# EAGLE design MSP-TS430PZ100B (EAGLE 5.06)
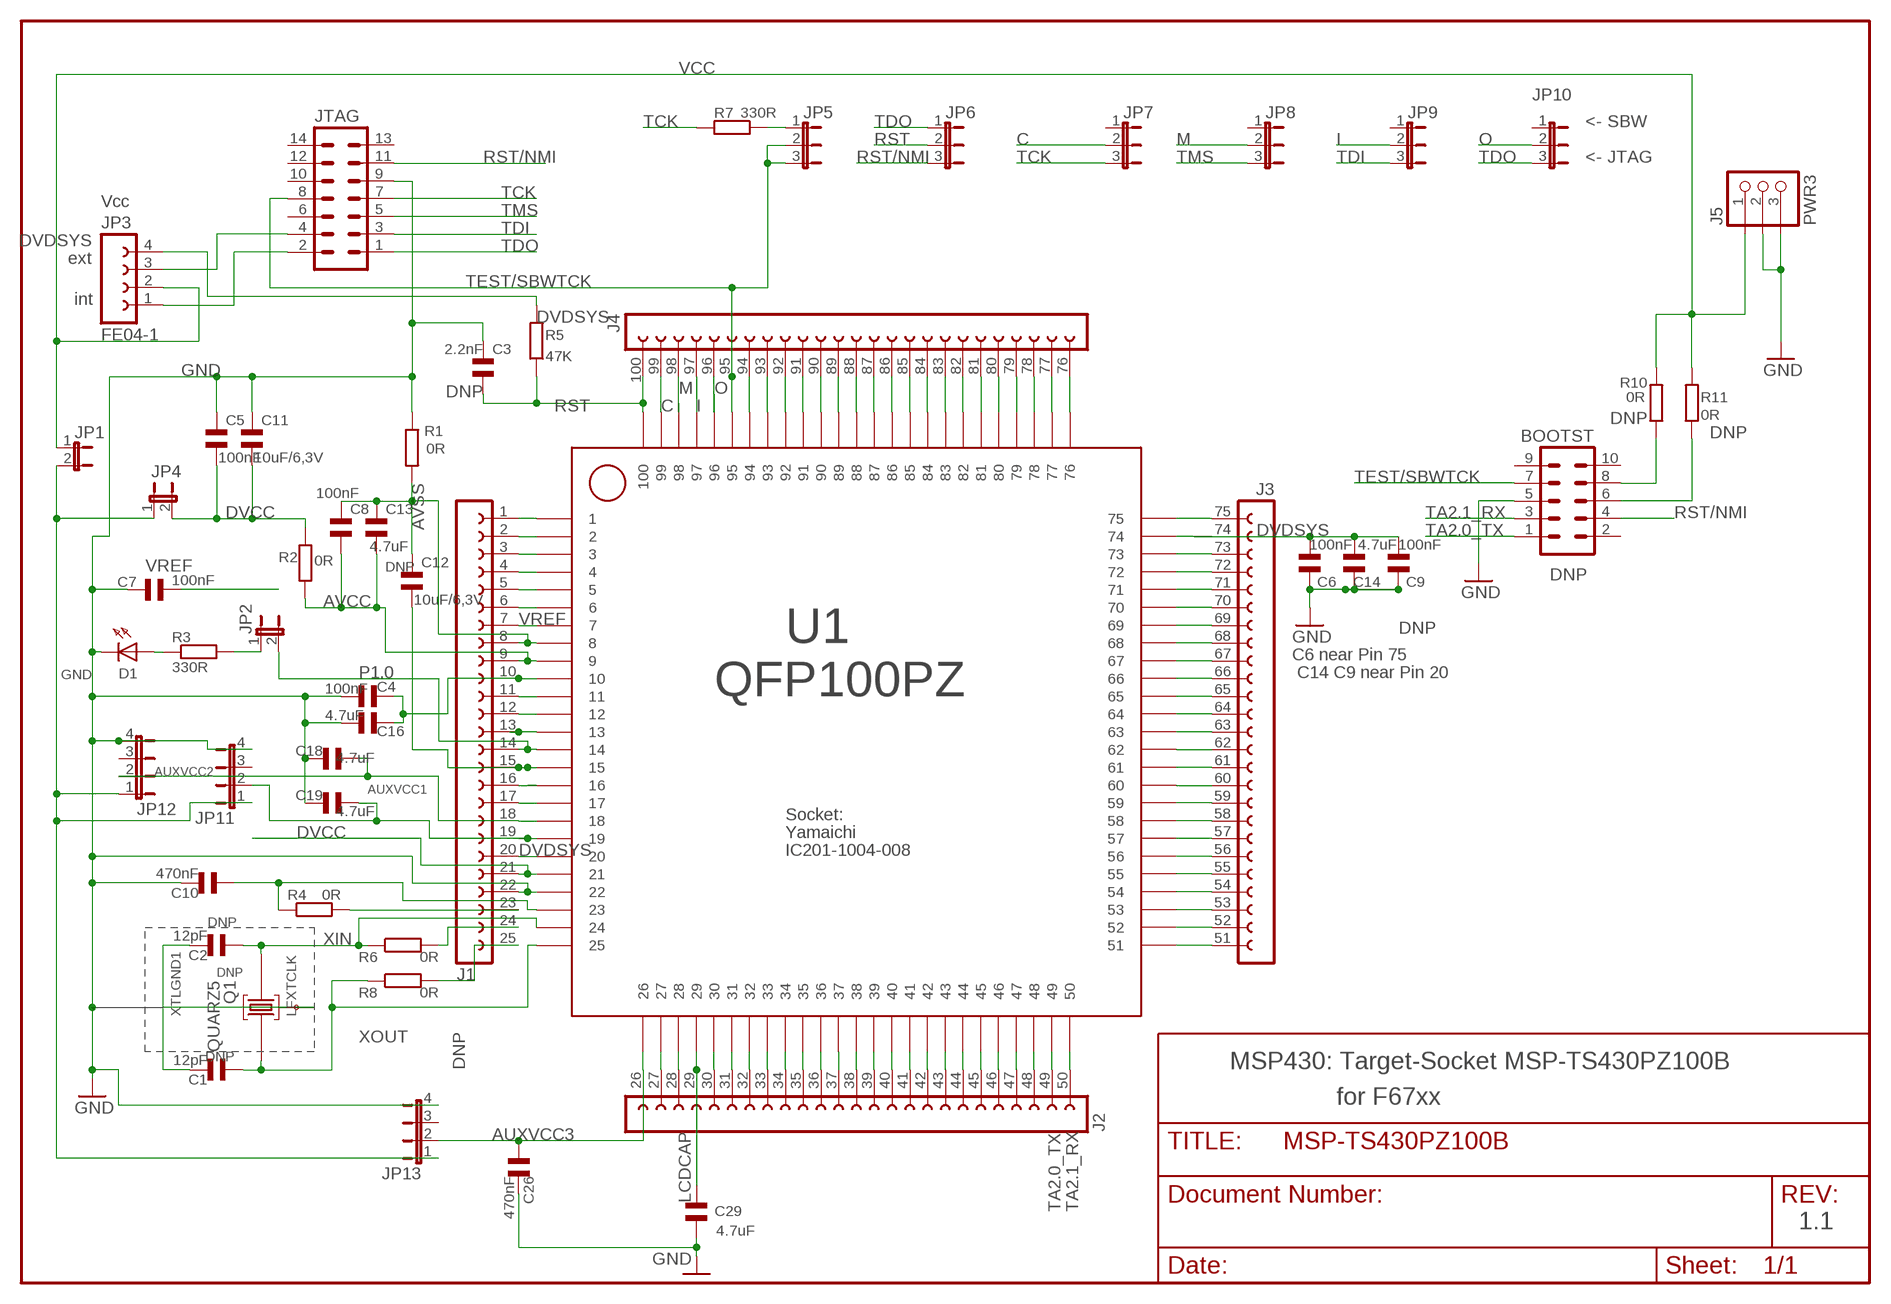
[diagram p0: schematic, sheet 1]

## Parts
BOOTST  ML10  [ML10]
C1  12pF  CSMD0805  [CSMD0805]
C2  12pF  CSMD0805  [CSMD0805]
C3  2.2nF  CSMD0805  [CSMD0805]
C4  100nF  CSMD0805  [CSMD0805]
C5  100nF  CSMD0805  [CSMD0805]
C6  100nF  CSMD0805  [CSMD0805]
C7  100nF  CSMD0805  [CSMD0805]
C8  100nF  CSMD0805  [CSMD0805]
C9  100nF  CSMD0805  [CSMD0805]
C10  470nF  CSMD0805  [CSMD0805]
C11  10uF/6,3V  CSMD0805  [CSMD0805]
C12  10uF/6,3V  CSMD0805  [CSMD0805]
C13  4.7uF  CSMD0805  [CSMD0805]
C14  4.7uF  CSMD0805  [CSMD0805]
C16  4.7uF  CSMD0805  [CSMD0805]
C18  4.7uF  CSMD0805  [CSMD0805]
C19  4.7uF  CSMD0805  [CSMD0805]
C26  470nF  CSMD0805  [CSMD0805]
C29  4.7uF  CSMD0805  [CSMD0805]
D1  LED30805  [DIODE_0805]
J1  FE25-1A1  [FE25-1A1]
J2  FE25-1A2  [FE25-1A2]
J3  FE25-1A3  [FE25-1A3]
J4  FE25-1A4  [FE25-1A4]
J5  PWR3  [PWR3]
JP1  JP1E  [JP1]
JP2  JP1E  [JP1]
JP3  FE04-1  [FE04-1]
JP4  JP1E  [JP1]
JP5  JP2ESMALLPAD  [JP2Z]
JP6  JP2ESMALLPAD  [JP2Z]
JP7  JP2ESMALLPAD  [JP2Z]
JP8  JP2ESMALLPAD  [JP2Z]
JP9  JP2ESMALLPAD  [JP2Z]
JP10  JP2ESMALLPAD  [JP2Z]
JP11  JP4E  [JP4]
JP12  JP4E  [JP4]
JP13  JP4E  [JP4]
JTAG  ML14  [ML14]
Q1  QUARZ5  [QUARZ5]
R1  0R  R_0805  [0805]
R2  0R  R_0805  [0805]
R3  330R  R_0805  [0805]
R4  0R  R_0805  [0805]
R5  47K  R_0805  [0805]
R6  0R  R_0805  [0805]
R7  330R  R_0805  [0805]
R8  0R  R_0805  [0805]
R10  0R  R_0805  [0805]
R11  0R  R_0805  [0805]
U1  QFP100PZ  [QFP100PZ]

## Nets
AUXVCC1: C19.2 J1.19 JP11.2 U1.P19
AUXVCC2: C18.2 J1.18 JP12.2 U1.P18
AUXVCC3: C26.1 J2.26 JP13.2 U1.P26
AVCC: C8.1 C13.1 J1.9 R2.1 U1.P9
AVSS: C8.2 C12.2 C13.2 J1.8 R1.2 U1.P8
C: J4.99 JP7.2 U1.P99
DVCC: C5.1 C11.1 J1.21 JP4.2 R2.2 U1.P21
DVDSYS: C6.2 C9.2 C14.2 J1.20 J3.74 JP3.4 R5.2 U1.P20 U1.P74
GND: BOOTST.5 C3.1 C4.2 C5.2 C6.1 C7.2 C9.1 C10.2 C11.2 C14.1 C16.2 C18.1 C19.1 C26.2 C29.1 D1.K J1.22 J5.2 J5.3 JP11.4 JP12.4 JP13.4 JTAG.9 R1.1 U1.P22
I: J4.97 JP9.2 U1.P97
LCDCAP: C29.2 J2.29 U1.P29
M: J4.98 JP8.2 U1.P98
MSP_VCC: JP1.2 JP4.1 JP11.1 JP12.1 JP13.1
N$1: JP2.1 R3.2
N$2: J3.62 U1.P62
N$3: J1.11 U1.P11
N$4: J3.64 U1.P64
N$5: J4.83 U1.P83
N$6: J4.76 U1.P76
N$7: JP3.1 JTAG.2
N$8: J4.85 U1.P85
N$9: J1.3 U1.P3
N$10: J4.84 U1.P84
N$11: J4.82 U1.P82
N$12: J1.4 U1.P4
N$13: J1.5 U1.P5
N$14: J4.81 U1.P81
N$15: J1.6 U1.P6
N$16: J2.46 U1.P46
N$17: J4.94 U1.P94
N$18: D1.A R3.1
N$20: J4.93 U1.P93
N$21: J2.42 U1.P42
N$22: J1.1 U1.P1
N$23: JP3.3 JTAG.4
N$24: J4.92 U1.P92
N$25: J3.60 U1.P60
N$26: J1.13 U1.P13
N$27: J4.91 U1.P91
N$28: J1.24 R6.2
N$29: J1.25 R8.2
N$31: J2.37 U1.P37
N$32: J1.23 R4.2
N$33: J3.61 U1.P61
N$34: J2.39 U1.P39
N$35: J4.90 U1.P90
N$36: J3.63 U1.P63
N$37: J1.12 U1.P12
N$39: J4.89 U1.P89
N$40: J2.28 U1.P28
N$42: BOOTST.8 R10.1
N$43: J2.30 U1.P30
N$44: J2.31 U1.P31
N$45: J2.32 U1.P32
N$46: J2.33 U1.P33
N$47: J2.34 U1.P34
N$48: J2.35 U1.P35
N$49: BOOTST.6 R11.1
N$50: J2.36 U1.P36
N$51: J4.88 U1.P88
N$52: J4.87 U1.P87
N$53: J1.2 U1.P2
N$54: J2.38 U1.P38
N$55: J2.40 U1.P40
N$56: J2.41 U1.P41
N$57: JP5.1 R7.1
N$58: J2.43 U1.P43
N$59: J2.44 U1.P44
N$60: J2.45 U1.P45
N$62: J2.47 U1.P47
N$63: J2.48 U1.P48
N$66: J3.51 U1.P51
N$67: J3.52 U1.P52
N$68: J3.53 U1.P53
N$69: J4.86 U1.P86
N$70: J3.54 U1.P54
N$71: J3.55 U1.P55
N$72: J3.56 U1.P56
N$73: J3.57 U1.P57
N$74: J3.58 U1.P58
N$75: J3.59 U1.P59
N$80: J4.80 U1.P80
N$81: J4.79 U1.P79
N$84: J4.78 U1.P78
N$86: J4.77 U1.P77
N$87: J3.65 U1.P65
N$88: J3.66 U1.P66
N$89: J3.67 U1.P67
N$90: J3.68 U1.P68
N$91: J3.69 U1.P69
N$92: J3.70 U1.P70
N$93: J3.71 U1.P71
N$94: J3.72 U1.P72
N$95: J3.73 U1.P73
N$97: J3.75 U1.P75
O: J4.96 JP10.2 U1.P96
P1.0: J1.14 JP2.2 U1.P14
P2.2: J2.27 U1.P27
RST: C3.2 J4.100 JP6.2 R5.1 U1.P100
RST/NMI: BOOTST.4 JP6.3 JTAG.11
TA2.0_TX: BOOTST.1 J2.49 U1.P49
TA2.1_RX: BOOTST.3 J2.50 U1.P50
TCK: JP7.3 JTAG.7 R7.2
TDI: JP9.3 JTAG.3
TDO: JP6.1 JP10.3 JTAG.1
TEST/SBWTCK: BOOTST.7 J4.95 JP5.2 JP5.3 JTAG.8 U1.P95
TMS: JP8.3 JTAG.5
UCA0RXD: J1.16 U1.P16
UCA0TXD: J1.17 U1.P17
VASYS: C4.1 C16.1 J1.10 U1.P10
VCC: J5.1 JP1.1 JP3.2 R10.2 R11.2
VCORE: C10.1 R4.1 U1.P23
VEREF+: C12.1 J1.15 U1.P15
VREF: C7.1 J1.7 U1.P7
XIN: C2.1 Q1.2 R6.1 U1.P24
XOUT: C1.1 Q1.1 R8.1 U1.P25
XTLGND1: C1.2 C2.2 Q1.GND@0
Unconnected: BOOTST.2 BOOTST.9 BOOTST.10 JP7.1 JP8.1 JP9.1 JP10.1 JP11.3 JP12.3 JP13.3 JTAG.6 JTAG.10 JTAG.12 JTAG.13 JTAG.14

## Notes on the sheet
- <- SBW
- <- JTAG
- Vcc
- DVDSYS
- ext
- int
- DNP
- DNP
- DNP
- DNP
- DNP
- DNP
- C6 near Pin 75
- GND
- C14 C9 near Pin 20
- Socket:
- Yamaichi
- IC201-1004-008
- DNP
- DNP
- LFXTCLK
- DNP
- DNP | MSP430: Target-Socket MSP-TS430PZ100B
- for F67xx
- 1.1

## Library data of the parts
BOOTST = con-ml:ML10
C1-C14 C16 C18 C19 C26 C29 = cap:CSMD0805
D1 = MSP430:LED3
J1 = CON-LSTA:FE25-1A1
J2 = CON-LSTA:FE25-1A2
J3 = CON-LSTA:FE25-1A3
J4 = CON-LSTA:FE25-1A4
J5 = MSP430:PWR3
JP1 JP2 JP4 = jumper:JP1E: JUMPER
JP3 = scon-lsta:FE04-1
JP5-JP10 = jumper:JP2E: JUMPER
JP11-JP13 = sjumper:JP4E: JUMPER
JTAG = con-ml:ML14
Q1 = sMSP430:QUARZ5
R1-R8 R10 R11 = smd:R_0805
U1 = MSP430:QFP100PZ

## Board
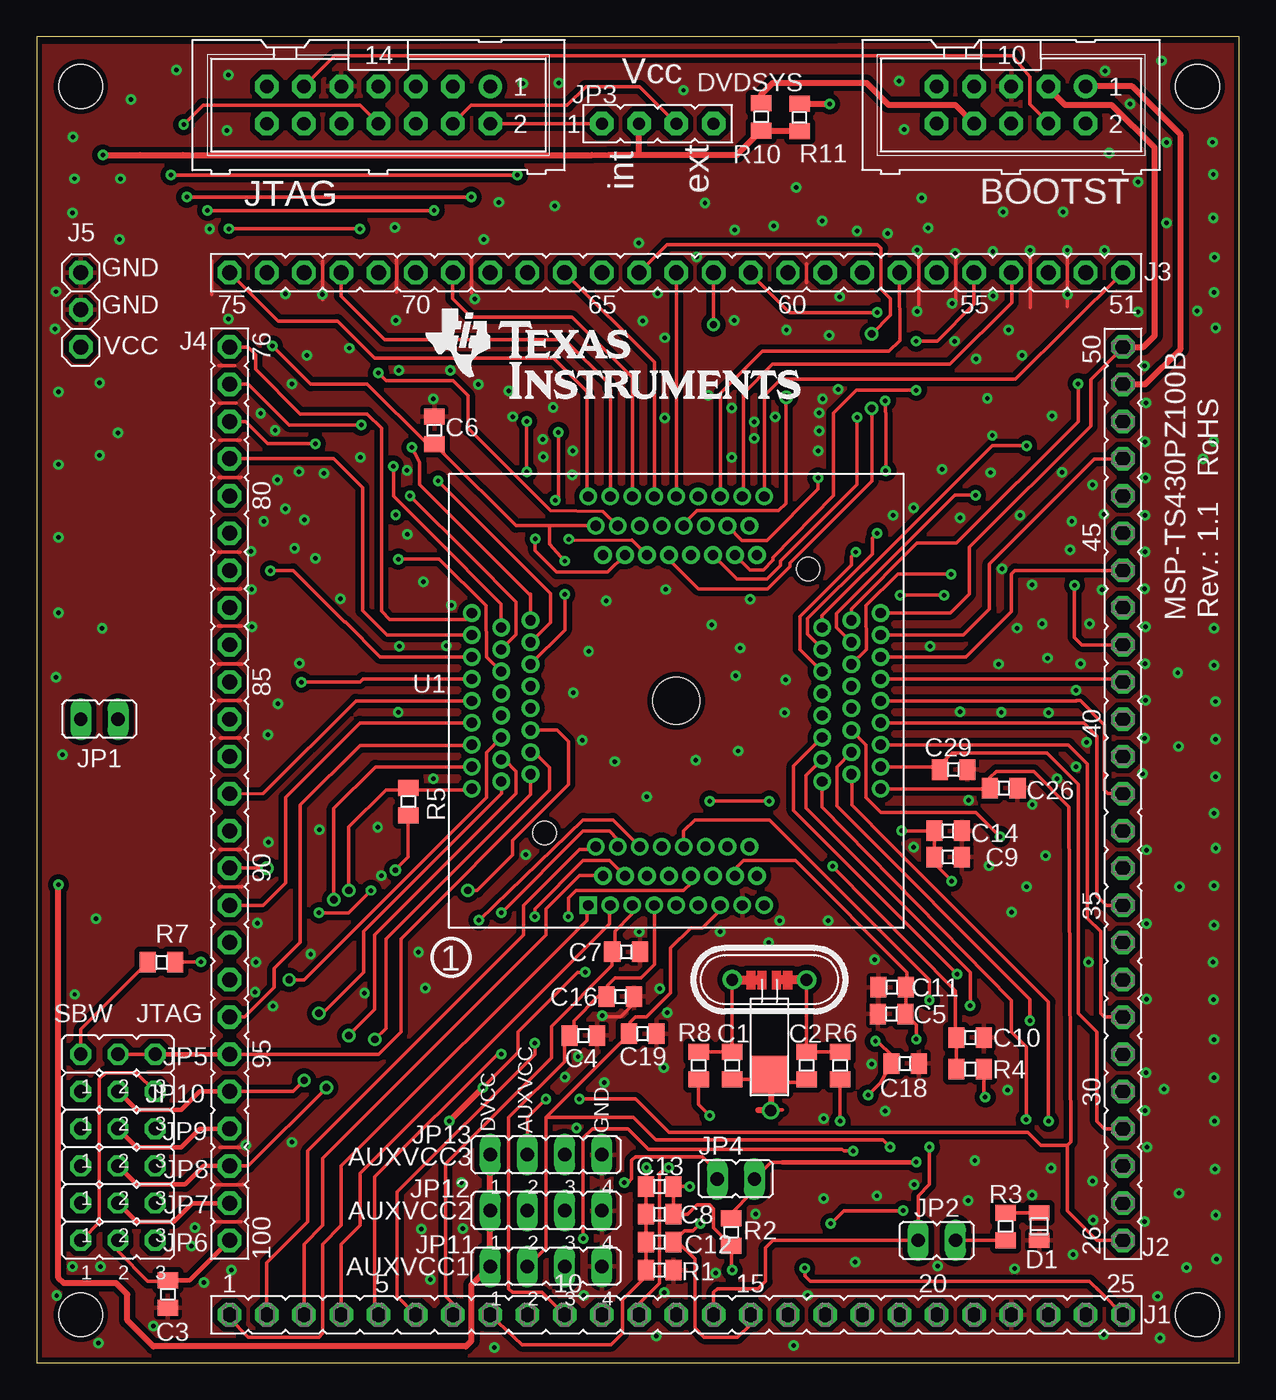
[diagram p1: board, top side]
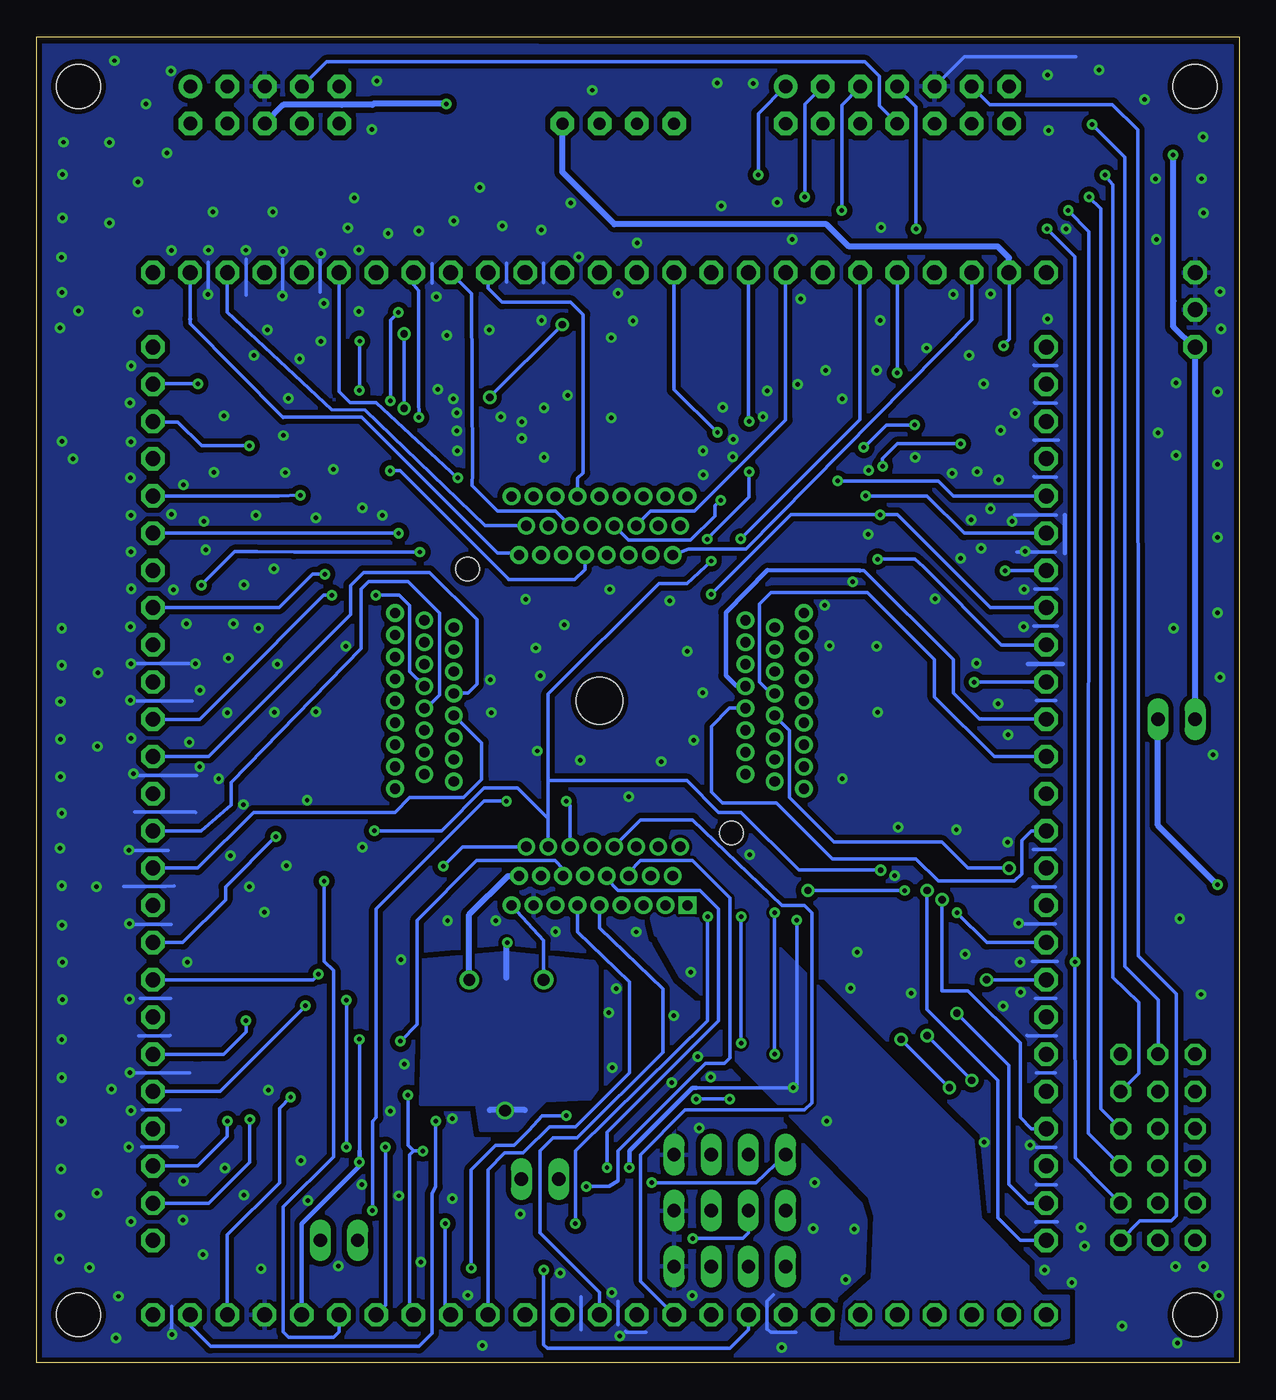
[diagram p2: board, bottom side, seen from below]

Size 82.07 x 90.5 mm. Coordinates in mm from the lower left corner, seen from the top.
Outline: 0,0 82.06,0 82.06,90.5 0,90.5 0,0
Copper layers (1*16): Top 0.035mm / dielectric 1.5mm / Bottom 0.035mm
Design rules "default *": minimum track width 8mil, minimum drill 12mil, track to track 8mil, track to pad 8mil, pad to pad 8mil, via to via 8mil, smd to smd 8mil, copper to edge 8mil, drill to drill 8mil, minimum pad ring 10mil, minimum via ring 8mil, stop-mask expansion 0mil, vias tented up to drill 25mil, thermal gap 10mil
Holes 3 mm at 3.01,3.28 3.01,87.1 79.21,3.28 79.21,87.1
tRestrict: area 44.1,55.8 to 45.7,56.3; area 42.6,57.9 to 44.2,58.5; area 30.4,44.1 to 30.9,45.7; area 56.3,43.6 to 56.8,45.2
bRestrict: area 44.1,55.8 to 45.8,56.3; area 42.6,57.9 to 44.2,58.5; area 30.3,44.1 to 30.9,45.7

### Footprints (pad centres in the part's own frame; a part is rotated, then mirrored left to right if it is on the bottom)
ML10 = drill 0.914 pad 1.6 round: 1 -5.08,-1.27 | drill 0.914 pad 1.6 octagon: 2 -5.08,1.27; 3 -2.54,-1.27; 4 -2.54,1.27; 5 0,-1.27; 6 0,1.27; 7 2.54,-1.27; 8 2.54,1.27; 9 5.08,-1.27; 10 5.08,1.27
CSMD0805 = smd 1.092 x 1.397: 1 -0.94,0; 2 0.94,0
DIODE_0805 = smd 1 x 1.4: A -0.94,0; K 0.94,0
FE25-1A1 = drill 1.016 pad 1.6 octagon: 1 -30.48,0; 2 -27.94,0; 3 -25.4,0; 4 -22.86,0; 5 -20.32,0; 6 -17.78,0; 7 -15.24,0; 8 -12.7,0; 9 -10.16,0; 10 -7.62,0; 11 -5.08,0; 12 -2.54,0; 13 0,0; 14 2.54,0; 15 5.08,0; 16 7.62,0; 17 10.16,0; 18 12.7,0; 19 15.24,0; 20 17.78,0; 21 20.32,0; 22 22.86,0; 23 25.4,0; 24 27.94,0; 25 30.48,0
FE25-1A2 = drill 1.016 pad 1.6 octagon: 26 -30.48,0; 27 -27.94,0; 28 -25.4,0; 29 -22.86,0; 30 -20.32,0; 31 -17.78,0; 32 -15.24,0; 33 -12.7,0; 34 -10.16,0; 35 -7.62,0; 36 -5.08,0; 37 -2.54,0; 38 0,0; 39 2.54,0; 40 5.08,0; 41 7.62,0; 42 10.16,0; 43 12.7,0; 44 15.24,0; 45 17.78,0; 46 20.32,0; 47 22.86,0; 48 25.4,0; 49 27.94,0; 50 30.48,0
FE25-1A3 = drill 1.016 pad 1.6 octagon: 51 -30.48,0; 52 -27.94,0; 53 -25.4,0; 54 -22.86,0; 55 -20.32,0; 56 -17.78,0; 57 -15.24,0; 58 -12.7,0; 59 -10.16,0; 60 -7.62,0; 61 -5.08,0; 62 -2.54,0; 63 0,0; 64 2.54,0; 65 5.08,0; 66 7.62,0; 67 10.16,0; 68 12.7,0; 69 15.24,0; 70 17.78,0; 71 20.32,0; 72 22.86,0; 73 25.4,0; 74 27.94,0; 75 30.48,0
FE25-1A4 = drill 1.016 pad 1.6 octagon: 76 -30.48,0; 77 -27.94,0; 78 -25.4,0; 79 -22.86,0; 80 -20.32,0; 81 -17.78,0; 82 -15.24,0; 83 -12.7,0; 84 -10.16,0; 85 -7.62,0; 86 -5.08,0; 87 -2.54,0; 88 0,0; 89 2.54,0; 90 5.08,0; 91 7.62,0; 92 10.16,0; 93 12.7,0; 94 15.24,0; 95 17.78,0; 96 20.32,0; 97 22.86,0; 98 25.4,0; 99 27.94,0; 100 30.48,0
PWR3 = drill 1.016 pad 1.6 octagon: 1 -2.54,0; 2 0,0; 3 2.54,0
JP1 = drill 0.914 long: 1 0,-1.27; 2 0,1.27
FE04-1 = drill 0.813 pad 1.6 octagon: 1 -3.81,0; 2 -1.27,0; 3 1.27,0; 4 3.81,0
JP2Z = drill 0.914 octagon: 1 -2.54,0; 2 0,0; 3 2.54,0
JP4 = drill 0.914 long: 1 -3.81,0; 2 -1.27,0; 3 1.27,0; 4 3.81,0
ML14 = drill 0.914 pad 1.6 round: 1 -7.62,-1.27 | drill 0.914 pad 1.6 octagon: 2 -7.62,1.27; 3 -5.08,-1.27; 4 -5.08,1.27; 5 -2.54,-1.27; 6 -2.54,1.27; 7 0,-1.27; 8 0,1.27; 9 2.54,-1.27; 10 2.54,1.27; 11 5.08,-1.27; 12 5.08,1.27; 13 7.62,-1.27; 14 7.62,1.27
QUARZ5 = drill 0.813 round: 1 1.53,1.773; 2 1.52,-3.303 | smd 2.54 x 2.54: GND@0 -4.941,-0.762
0805 = smd 1.092 x 1.397: 1 -0.94,0; 2 0.94,0
QFP100PZ = drill 0.7 pad 1 square: P1 -6,-13.95 | drill 0.7 pad 1 round: P2 -5.5,-9.95; P3 -5,-11.95; P4 -4.5,-13.95; P5 -4,-9.95; P6 -3.5,-11.95; P7 -3,-13.95; P8 -2.5,-9.95; P9 -2,-11.95; P10 -1.5,-13.95; P11 -1,-9.95; P12 -0.5,-11.95; P13 0,-13.95; P14 0.5,-9.95; P15 1,-11.95; P16 1.5,-13.95; P17 2,-9.95; P18 2.5,-11.95; P19 3,-13.95; P20 3.5,-9.95; P21 4,-11.95; P22 4.5,-13.95; P23 5,-9.95; P24 5.5,-11.95; P25 6,-13.95; P26 13.95,-6; P27 9.95,-5.5; P28 11.95,-5; P29 13.95,-4.5; P30 9.95,-4; P31 11.95,-3.5; P32 13.95,-3; P33 9.95,-2.5; P34 11.95,-2; P35 13.95,-1.5; P36 9.95,-1; P37 11.95,-0.5; P38 13.95,0; P39 9.95,0.5; P40 11.95,1; P41 13.95,1.5; P42 9.95,2; P43 11.95,2.5; P44 13.95,3; P45 9.95,3.5; P46 11.95,4; P47 13.95,4.5; P48 9.95,5; P49 11.95,5.5; P50 13.95,6; P51 6,13.95; P52 5.5,9.95; P53 5,11.95; P54 4.5,13.95; P55 4,9.95; P56 3.5,11.95; P57 3,13.95; P58 2.5,9.95; P59 2,11.95; P60 1.5,13.95; P61 1,9.95; P62 0.5,11.95; P63 0,13.95; P64 -0.5,9.95; P65 -1,11.95; P66 -1.5,13.95; P67 -2,9.95; P68 -2.5,11.95; P69 -3,13.95; P70 -3.5,9.95; P71 -4,11.95; P72 -4.5,13.95; P73 -5,9.95; P74 -5.5,11.95; P75 -6,13.95; P76 -13.95,6; P77 -9.95,5.5; P78 -11.95,5; P79 -13.95,4.5; P80 -9.95,4; P81 -11.95,3.5; P82 -13.95,3; P83 -9.95,2.5; P84 -11.95,2; P85 -13.95,1.5; P86 -9.95,1; P87 -11.95,0.5; P88 -13.95,0; P89 -9.95,-0.5; P90 -11.95,-1; P91 -13.95,-1.5; P92 -9.95,-2; P93 -11.95,-2.5; P94 -13.95,-3; P95 -9.95,-3.5; P96 -11.95,-4; P97 -13.95,-4.5; P98 -9.95,-5; P99 -11.95,-5.5; P100 -13.95,-6 | hole 3.2: 0,0 | hole 1.6: -9,-9; 9,9

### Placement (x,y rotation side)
BOOTST  66.5,85.83 180 top
C1  47.46,20.3 270 top
C2  52.54,20.3 270 top
C3  8.95,4.7 90 top
C4  37.3,22.33 0 top
C5  58.36,23.81 180 top
C6  27.14,63.63 270 top
C7  40.22,28.05 0 top
C8  42.51,10.14 180 top
C9  62.19,34.52 180 top
C10  63.72,22.2 0 top
C11  58.38,25.63 180 top
C12  42.51,8.23 180 top
C13  42.51,12.04 180 top
C14  62.19,36.3 180 top
C16  39.84,25 0 top
C18  59.27,20.43 180 top
C19  41.36,22.46 180 top
C26  66,39.22 0 top
C29  62.57,40.49 180 top
D1  68.41,9.3 270 top
J1  43.65,3.28 0 top
J2  74.13,38.84 90 top
J3  43.65,74.4 180 top
J4  13.17,38.84 270 top
J5  3.01,71.86 90 top
JP1  4.28,43.92 270 top
JP2  61.43,8.36 90 top
JP3  42.38,84.56 0 top
JP4  47.71,12.55 270 top
JP5  5.55,21.06 0 top
JP6  5.55,8.36 0 top
JP7  5.55,10.9 0 top
JP8  5.55,13.44 0 top
JP9  5.55,15.98 0 top
JP10  5.55,18.52 0 top
JP11  34.76,6.58 0 top
JP12  34.76,10.39 0 top
JP13  34.76,14.2 0 top
JTAG  23.33,85.83 180 top
Q1  49.24,24.62 90 top
R1  42.51,6.33 180 top
R2  47.41,8.93 90 top
R3  66.13,9.3 270 top
R4  63.72,20.04 0 top
R5  25.36,38.28 270 top
R6  54.83,20.3 270 top
R7  8.52,27.33 0 top
R8  45.17,20.3 270 top
R10  49.44,85.02 270 top
R11  52.06,84.98 270 top
U1  43.65,45.17 0 top
U$2  [LABEL_2008_TPLACE]  35.37,67.77 0 top

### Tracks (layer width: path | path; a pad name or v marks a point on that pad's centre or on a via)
AUXVCC1  (via drill 0.3)
  Top 0.254: U1.P19 46.65,30.92 45.43,29.7 44.67,29.7 43.27,28.3 43.27,25.25 41.62,23.6 40.86,23.6 40.48,23.22 40.48,22.51 C19.2 40.42,22.41 34.76,16.74 | v58.26,14.71 57.75,15.22 42.25,15.22 40.73,16.74 34.76,16.74 | 34.76,16.74 34.76,7.85 JP11.2
  Bottom 0.254: v58.26,14.71 58.26,3.92 J1.19
AUXVCC2  (via drill 0.3)
  Top 0.254: v55.72,14.46 55.08,14.46 54.95,14.58 41.74,14.58 40.35,15.98 37.94,15.98 37.3,15.35 v37.3,8.49 | v56.73,18.27 57.57,19.1 C18.2 58.38,20.48 58.38,20.93 57.37,21.95 v57.24,21.95
  Bottom 0.254: U1.P18 46.15,33.72 46.7,34.27 52.03,34.27 56.1,30.2 56.1,23.09 v57.24,21.95 | J1.18 56.6,3.53 56.6,14.2 56.35,14.46 | v55.72,14.46 56.35,14.46 | v56.73,18.27 56.73,14.84 56.35,14.46 | v37.3,8.49 33.87,8.49 33.49,8.87 JP12.2
AUXVCC3  (via drill 0.3)
  Top 0.254: J2.26 72.35,8.36 70.32,10.39 70.32,14.84 | JP13.2 33.49,16.74 v34.76,18.01 | v37.05,18.01 40.86,18.01 43.14,15.73 67.65,15.73 68.54,14.84 70.32,14.84 | U1.P26 65.06,39.17 C26.1 65.06,39.93 65.49,40.36 68.03,40.36 70.45,37.95 70.57,15.09 70.32,14.84
  Bottom 0.254: v34.76,18.01 v37.05,18.01
AVCC  (via drill 0.3)
  Top 0.254: v44.56,12.04 C13.1 C8.1 44.41,10.14 45.05,10.77 45.94,10.77 46.19,10.52 46.19,9.21 R2.1 47.41,6.33 v47.46,6.33
  Bottom 0.254: U1.P9 41.65,33.47 40.86,34.27 37.3,34.27 34.76,31.73 34.76,20.81 35.14,20.43 36.41,20.43 42.38,14.46 42.38,12.42 43.02,12.04 v44.56,12.04 | v47.46,6.33 47.46,1.25 47.21,0.99 34.76,0.99 33.49,2.26 J1.9
AVSS  (via drill 0.3)
  Top 0.254: J1.8 33.11,1.25 39.2,1.25 39.97,2.01 39.97,4.3 41.63,5.96 R1.2 C12.2 C8.2 C13.2 | U1.P8 41.15,35.24 39.33,37.06 37.3,37.06 v30.19,30.2 | C13.2 41.57,12.12 | v41.62,13.31 41.62,12.09 C13.2 | v37.43,26.65 36.92,26.65 32.85,22.58 32.85,21.19 v30.44,18.77
  Top 0.406: v30.44,18.77 v28.16,16.49
  Bottom 0.254: v30.19,30.2 30.19,18.77 v30.44,18.77 37.05,18.77
  Bottom 0.305: 37.05,18.77 37.3,18.77 41.62,14.46 v41.62,13.31
  pour Bottom: 27.17,1.64 26.9,4.05 25.04,5.75 24.85,10.06 25.23,11.28 34.76,21.06 35.71,24.3 38.13,26.35 39.59,28.93 39.46,29.19 39.59,29.06 39.84,29.19 40.09,30.33 38.7,36.27 37.3,36.27 35.01,34.01 32.22,31.47 31.97,28.93 20.51,17.48 18.16,15.19 17.66,9.87 15.2,7.34 14.44,6.58 14.44,5.57 13.42,4.55 11.65,4.55 11.65,1.74 12.19,1.61
C  (via drill 0.5)
  Top 0.254: U1.P99 31.71,39.66 31.71,38.84 22.31,29.44 22.31,26.65 19.52,23.85 v19.27,23.85
  Top 0.305: JP7.2 6.82,9.63 9.36,9.63 10.63,10.9 J4.99
  Bottom 0.254: J4.99 14.44,10.9 15.71,12.17 15.71,20.3 v19.27,23.85
DVCC  (via drill 0.3)
  Top 0.254: U1.P21 47.65,33.7 48.22,34.27 51.78,34.27 59.4,26.65 59.4,25.71 C11.1 59.32,23.83 C5.1 60.03,23.07 v60.03,22.08 | R2.2 47.41,10.21 48.86,11.66 JP4.2 50.13,13.69 50.85,13.69
  Top 0.305: 50.85,13.69 v60.03,13.69
  Bottom 0.254: 60.03,14.46 v60.03,22.08
  Bottom 0.305: J1.21 63.97,9.5 60.03,13.44 v60.03,13.69 60.03,14.46
DVDSYS  (via drill 0.3, 0.38)
  Top 0.254: 35.01,57.12 32.7,57.12 27.82,62 | 35.01,57.12 U1.P74 | v36.03,54.71 35.01,55.86 35.01,57.12 | 27.13,62.69 C6.2 | 27.13,62.69 27.12,62.7 | 27.13,62.69 27.82,62 | 27.82,62 27.82,62.04 27.14,62.72 26.63,62.72 22.57,66.78 18.7,66.78 v16.09,69.39 | v59.02,36.3 C14.2 C9.2 61.25,34.06 v62.45,32.87 | R5.2 25.36,34.52 v24.47,33.63
  Bottom 0.254: J3.74 15.69,74.38 15.7,69.85 16.09,69.46 v16.09,69.39 | 47.15,39.73 47.15,36.88 | 47.15,39.73 47.15,45.63 39.59,53.19 37.68,53.19 v36.03,54.71 | 47.15,36.88 U1.P20 | v59.02,36.3 54.45,36.3 51.52,39.22 49.24,39.22 47.15,37.13 47.15,36.88 | v62.45,32.87 62.45,27.41 61.81,26.77 61.81,14.07 65.24,10.65 65.24,2.14 64.86,1.76 61.81,1.76 61.43,2.14 J1.20 | v24.47,33.63 30.06,33.63 34,37.57 35.52,37.57 37.68,39.73 47.15,39.73
  Bottom 0.406: JP3.4 46.19,81.26 42.63,77.7 28.16,77.7 26.63,76.18 16.47,76.18 15.71,75.42 J3.74
GND  (via drill 0.3)
  Top 0.254: 19.53,72.56 19.53,75.18 | 24.57,73.06 24.57,75.3 | 11.96,72.89 11.96,75.18 | 29.69,73.02 29.69,75.34 | 60.19,72.22 60.19,75.95 | 62.72,72.31 62.72,75.76 | 67.81,72.02 67.81,75.76 | 70.34,72.07 70.34,75.95 | 14,50.27 12.37,50.27 | 12.4,47.7 14.01,47.7 | 13.91,45.19 12.37,45.19 | 12.39,52.81 13.92,52.81 13.94,52.82 | 13.89,55.34 12.43,55.34 | 12.42,68.04 13.53,68.04 | 12.46,65.5 13.62,65.5 | 12.42,60.42 13.94,60.42 13.97,60.45 | 12.52,42.63 13.88,42.63 13.89,42.64 | 13.94,35.04 12.48,35.04 | 12.45,32.49 13.98,32.49 14.01,32.52 | 12.48,14.71 13.91,14.71 13.92,14.73 | 12.27,12.17 14.06,12.17 14.07,12.18 | 12.28,9.63 13.95,9.63 13.97,9.62 | 12.48,62.96 13.89,62.96 | 52.54,73.73 52.54,75.02 | C16.2 40.98,25 40.98,24.74 39.84,23.6 38.69,23.6 v38.6,23.69
  Bottom 0.254: 42.38,2.6 42.38,4.21 | 44.91,2.27 44.91,4.5 | 72.47,14.73 74.9,14.73 | 72.28,17.26 74.85,17.26 | 72.91,24.87 75,24.87 | 75.09,22.3 73,22.3 72.96,22.35 | 12.49,22.3 14.44,22.3 14.48,22.35 | 13.85,19.78 12.54,19.78 | 15.16,55.33 12.54,55.33 | 12.49,57.86 15.35,57.86 | 71.16,47.73 75.67,47.73 | 71.45,45.16 75.67,45.16 | 71.16,40.07 75.67,40.07 | 75.38,37.59 71.26,37.59 71.21,37.54 | 73.08,34.97 75.48,34.97 | 76.11,32.5 73.26,32.5 72.67,32.55 | 72.88,29.92 75.72,29.92 | 71.64,19.78 75.62,19.78 | 31.77,4.65 32.23,4.19 32.23,2.31 32.18,2.31 31.95,2.08 30.23,2.08 | 62.73,73.07 62.73,75.31 | 65.27,72.72 65.27,75.31 | 67.76,72.87 67.76,75.31 | 70.35,72.67 70.35,75.11 | JTAG.9 18.75,89.14 11.17,89.14 | 14,50.27 12.42,50.27 | 12.51,45.19 13.85,45.19 | 13.94,52.81 12.45,52.81 | 12.45,68.06 13.98,68.06 14,68.07 | 12.48,65.5 13.95,65.5 13.97,65.51 | 13.92,62.96 12.34,62.96 | 14.03,62.98 14.01,62.96 13.92,62.96 | 12.48,60.43 13.98,60.43 14.01,60.46 | 12.54,35.04 14.06,35.04 | 12.55,32.47 14.07,32.47 14.09,32.49 | 12.55,29.94 14.66,29.94 | 13.87,27.4 12.4,27.4 | 13.85,14.71 12.51,14.71 | 12.49,12.17 13.83,12.17 13.85,12.18 | 12.4,9.62 13.88,9.62 13.89,9.61 | 40.47,2.09 41.82,2.09 41.87,2.15 | 13.9,62.95 13.92,62.96 | 13.91,24.87 12.53,24.87 | 13.87,27.4 14.11,27.4 | 13.86,27.41 13.87,27.4 | 72.86,3.87 72.86,2.38 72.87,2.36 | 47.46,73.71 47.46,75.03 | 50.01,73.76 50.01,75.04 | 55.08,75.02 55.08,73.68 55.07,73.67
  Bottom 0.305: 14.41,47.7 12.05,47.7 | 11.9,55.27 11.9,57.87
  other vias: 68.84,34.6 55.86,6.89 39.45,41.04 48.01,48.78 51.17,70.48 35.24,65.2 53.4,64.84 59.85,35.19 70.64,57.41 19.02,54.91 16.42,60.25 16.98,58.27 65.01,33.91 26.53,25.56 67.54,32.5 67.95,38.1 71.23,47.7 71.84,50.45 66.92,50.14 38.87,52 76.95,18.67 60.08,71.75 62.67,75.72 13.08,71.25 69.28,64.63 72.06,59.92 26.86,5.69 47.44,65.18 63.02,44.45 26.38,53.3 28.3,51.69 29.91,72.59 28.23,67.72 24.51,71.14 21.34,69.24 17.43,66.8 28.97,12.29 2.6,25.14 13.29,6.32 23.27,36.55 29.07,9.15 26.26,9.13 52.63,4.61 59.88,12.16 53.7,11.22 66.53,30.76 64.03,13.81 61.48,6.59 63.57,11.07 66.75,6.42 69.23,13.29 72.08,9.74 72.05,12.42 67.93,11.46 51.66,1.19 42.83,4.79 72.82,1.95 76.66,1.69 76.49,4.54 75.62,9.63 77.96,11.57 80.41,13.24 80.47,10.08 80.52,7.08 78.46,6.49 75.64,17.22 75.78,14.73 80.38,16.51 80.35,19.47 80.35,22.07 75.7,19.81 43.03,23.89 66.25,18.6 75.74,24.83 75.74,29.96 80.32,24.8 80.29,27.34 80.35,29.88 63.61,38.4 71.79,27.33 54.02,30.18 57.92,17.19 37.66,48.57 36.62,45.72 37.24,42.5 41.65,38.62 44.97,41.13 47.89,41.75 51.05,44.38 51.1,46.61 47.7,46.89 65.83,44.4 70.94,40.67 80.35,32.57 75.75,35 80.46,35.11 80.35,37.51 80.44,39.99 71.65,42.35 69.06,44.37 68.98,48.1 69.64,39.85 60.97,48.89 70.93,45.91 80.44,42.56 80.44,45.13 75.47,40.19 75.61,42.62 75.67,45.22 68.63,50.45 72.72,52.76 75.64,47.7 75.67,50.24 75.61,52.81 75.64,55.35 80.35,47.62 80.35,50.13 67.93,53.11 65.87,54.18 63.02,57.68 65.65,47.69 59.84,58.36 58.46,57.82 48.7,52.09 42.94,52.77 50.39,64.54 70.53,55.48 67.11,57.82 72.86,57.9 75.64,57.84 75.67,60.41 69.97,60.77 47.44,61.8 67.24,68.75 46.06,50.36 79.2,71.77 64.88,65.82 64.12,68.5 66.32,70.48 61.8,60.96 65.22,63.28 65.11,60.75 53.39,63.59 75.64,62.86 75.7,65.51 75.61,68.03 77.93,42.06 79.59,61.68 80.33,62.89 75.16,71.72 77.87,47.09 70.36,72.91 65.28,72.8 62.66,69.72 62.47,72.3 65.25,75.84 67.79,75.93 70.33,75.93 72.87,75.9 80.46,70.62 80.35,73.05 80.38,75.45 80.29,78.13 77.11,77.79 54.69,66.42 53.34,62.24 53.63,65.77 48.97,63.09 48.97,64.22 73.18,82.56 80.29,81.09 80.24,83.3 77.1,83.27 74.61,85.89 72.91,88.15 76.76,88.86 75.16,80.59 70.03,78.54 65.96,78.54 60.4,79.49 15.78,42.85 51.84,80.22 59.19,84.17 58.85,87.47 47.61,71.13 54.08,70.12 60.83,77.44 42.39,72.99 41.37,71.11 42.86,69.96 42.86,64.5 45.84,66.02 45.06,75.48 41.09,76.42 47.63,77.3 50.29,77.58 53.59,77.93 55.98,77.23 58.08,77.07 60.08,75.93 44.14,86.84 54.8,72.76 45.61,79.15 24.67,44.4 33.17,87.3 35.62,87.33 35.36,78.96 31.53,79.2 24.45,77.48 13.08,87.89 12.99,84.11 11.81,77.39 9.55,88.23 6.45,86.2 2.47,83.66 2.58,80.81 2.44,78.47 5.66,76.66 5.71,80.8 19.51,72.91 24.73,67.72 16.97,72.94 18.44,68.74 22.1,61.79 30.13,66.77 32.5,64.57 32.22,66.32 34.56,61.83 34.53,63.02 36.59,62.23 36.57,60.59 15.29,64.8 5.55,63.47 19.6,60.7 16.28,63.64 17.88,60.82 49.06,10.16 15.49,57.42 14.61,55.37 14.67,52.77 14.7,50.23 18.29,57.54 17.6,55.58 16.46,44.97 24.75,48.9 27.96,48.93 20.74,52.15 25.31,56.53 1.48,66.27 1.48,61.3 1.48,56.33 1.48,51.19 1.31,46.79 1.25,70.56 1.31,73.1 4.3,66.89 4.3,61.92 4.47,50.12 1.78,41.49 4.06,30.31 15.07,29.99 19.3,36.4 14.96,27.34 15.8,35.52 14.91,25.31 17.41,15.05 10.55,7.98 11.42,5.47 7.98,2.52 10.8,9.22 4.22,1.34 2.44,6.56 1.37,4.59 36.84,16.03 77.99,32.5 23.52,33.25 27.08,39.85 17.94,47.73 25.28,60.9 27.08,65.78 36.06,19.5 42.79,20.14 46.33,6.14 42.27,1.82 14.28,14.86 26.06,28.03 18.7,27.9 22.38,25.23 16.12,24.34 41.14,29.41 36.95,20.9 38.72,19.12 31.22,1.06 37.33,4.58 57.2,27.52 56.98,20.38 42.53,25.54 53.7,16.68 49.96,28.66 46.66,29.42 33.39,34.69 4.35,6.56 70.73,7.39 57.34,11.4 50.72,30.18 30.52,76.66
  pour Top (isolate 0.356, rank 2): 0.41,0.49 81.76,0.49 81.8,64.49 81.8,89.93 0.41,89.83
  pour Bottom (isolate 0.356, rank 2): 0.47,0.49 81.74,0.41 81.79,89.91 13.8,89.83 0.47,89.83
I  (via drill 0.5)
  Top 0.254: U1.P97 23.13,40.67 20.28,37.82 v20.28,31.6
  Top 0.305: JP9.2 6.82,14.71 9.87,14.71 11.14,15.98 J4.97
  Bottom 0.254: v20.28,31.6 20.28,25.38 18.5,25.38 14.95,21.82 14.95,16.74 14.19,15.98 J4.97
LCDCAP
  Top 0.254: J2.29 72.86,15.98 72.35,16.49 72.35,22.58 71.08,23.85 71.08,39.48 68.92,41.63 62.45,41.63 61.51,40.69 61.51,40.54 C29.2 61.58,40.67 U1.P29
M  (via drill 0.5)
  Top 0.254: v19.77,18.77 14.44,13.44 J4.98 | U1.P98 33.7,38.8 23.84,28.93 23.84,22.84 v23.08,22.08
  Top 0.305: JP8.2 6.82,12.17 10.12,12.17 11.39,13.44 J4.98
  Bottom 0.254: v19.77,18.77 v23.08,22.08
MSP_VCC  (via drill 0.3)
  Top 0.254: v40.09,12.3 40.35,12.3 40.6,12.55 40.6,13.82 40.86,14.07 45.43,14.07 46.44,13.06 JP4.1
  Top 0.406: v1.49,32.62 1.49,5.82 1.87,5.44 5.42,5.44 6.18,4.68 6.18,2.9 7.96,1.12 29.3,1.12 29.68,1.5 29.68,5.31 JP11.1 JP12.1 JP13.1
  Bottom 0.254: v40.09,12.3 32.98,12.3 JP13.1
  Bottom 0.406: JP1.2 5.55,36.68 v1.49,32.62
N$1
  Top 0.254: JP2.1 R3.2
N$2  (via drill 0.5)
  Top 0.254: U1.P62 44.15,57.25 45.05,58.14 50.64,58.14 51.14,58.65 v51.14,65.89 | v46.19,70.84 J3.62
  Bottom 0.254: v51.14,65.89 v46.19,70.84
N$3
  Bottom 0.254: 38.57,3.22 J1.11 40.86,5.57 40.86,14.2 37.81,17.25 29.68,17.25 29.17,17.76 29.17,30.71 29.68,31.22 31.2,31.22 37.3,37.06 40.86,37.06 42.7,35.22 U1.P11
N$4  (via drill 0.5)
  Top 0.254: U1.P64 43.15,54.83 45.17,52.81 49.87,52.81 51.4,54.33 51.4,54.59 56.98,60.18 v56.98,65.13 | v56.98,70.21 58.26,71.48 58.26,72.62 57.62,73.26 57.62,76.05 57.37,76.31 43.02,76.31 J3.64
  Bottom 0.254: v56.98,65.13 v56.98,70.21
N$5  (via drill 0.3)
  Top 0.254: U1.P83 36.05,50.02 v36.05,52.44
  Bottom 0.254: J4.83 16.98,51.54 23.33,57.89 24.49,57.89 v24.5,57.88 30.6,57.88 v36.05,52.44
N$6
  Top 0.254: U1.P76 29.26,50.73 24.09,50.73 24.09,50.74 23.54,51.3 23.53,51.3 23.53,63.79 22.57,64.75 18,64.75 14.95,67.8 14.95,68.81 14.44,69.32 J4.76
N$7
  Top 0.254: JTAG.2 JP3.1
N$8  (via drill 0.3)
  Top 0.254: v18.08,46.45 22.06,46.46 22.27,46.67 U1.P85
  Bottom 0.254: v18.08,46.45 14.66,46.45 14.65,46.46 J4.85
N$9
  Top 0.254: U1.P3 38.62,33.25 37.05,33.25 34.76,30.97 34.76,29.19 19.52,13.95 19.52,9.38 18.25,8.11 J1.3
N$10  (via drill 0.3)
  Top 0.254: v24.68,54.84 27.48,54.86 30.68,51.69 30.69,48.17 U1.P84
  Bottom 0.254: J4.84 16.22,49 21.55,54.33 22.14,54.84 v24.68,54.84
N$11  (via drill 0.3)
  Top 0.254: U1.P82 23.44,48.18 21.07,50.54 21.03,50.54 17.49,54.08 16,54.08 v15.96,54.05
  Bottom 0.254: J4.82 13.14,54.07 | J4.82 | v15.96,54.05 15.94,54.07 J4.82
N$12
  Top 0.254: J1.4 20.79,8.11 22.06,9.38 22.06,12.93 39.08,29.95 39.08,31.15 U1.P4
N$13  (via drill 0.3)
  Top 0.254: U1.P5 39.65,35.73 39.08,36.3 37.3,36.3 v31.71,30.71 | v31.71,21.06 31.46,21.06 23.08,12.68 23.08,3.53 J1.5
  Bottom 0.254: v31.71,21.06 v31.71,30.71
N$14  (via drill 0.3)
  Top 0.254: U1.P81 | U1.P81 | U1.P81 32.71,49.69 32.71,51.93 29.67,54.97 v25.48,59.16
  Bottom 0.254: J4.81 18.76,56.62 21.3,59.16 25.11,59.16 v25.48,59.16
N$15  (via drill 0.3)
  Top 0.254: J1.6 24.6,4.55 24.6,11.66 34,21.06 v34,21.82 | U1.P6 39.1,34.27 37.3,34.27 34,30.97 v34,30.46
  Bottom 0.254: v34,21.82 v34,30.46
N$16  (via drill 0.3)
  Top 0.254: U1.P46 54.58,50.19 54.58,51.15 59.55,56.1 62.66,59.2 v64.07,59.2
  Bottom 0.254: v64.07,59.2 65.54,59.15 74.09,59.15 74.09,59.14 74.1,59.15 J2.46 | J2.46 | J2.46
N$17
  Top 0.254: J4.94 14.19,23.6 16.22,25.63 16.22,26.9 18,28.68 18,38.08 22.06,42.14 29.67,42.14 U1.P94
N$18
  Top 0.254: R3.1 D1.A
N$20  (via drill 0.5)
  Top 0.254: v17.23,26.14 18.25,26.14 30.7,38.59 30.7,41.67 U1.P93
  Bottom 0.254: J4.93 v17.23,26.14
N$21  (via drill 0.3)
  Top 0.254: U1.P42 52.09,48.69 52.09,50.92 55.6,54.44 55.6,55.02 v55.91,55.33 | v70.83,53.06 70.83,49.51 71.34,49 J2.42
  Bottom 0.254: v55.91,55.33 64.5,55.33 67.02,55.35 67.53,55.35 68.54,55.35 v70.83,53.06
N$22
  Top 0.254: J1.1 13.17,3.03 14.44,1.76 19.27,1.76 19.52,2.01 19.52,8.11 20.79,9.38 20.79,13.44 37.55,30.2 37.55,31.13 U1.P1
N$23
  Top 0.254: JTAG.4 29.66,85.81 36.21,85.81 37.48,87.08 41.13,87.08 JP3.3
N$24  (via drill 0.3, 0.5)
  Top 0.254: U1.P92 35.51,43.17 36.28,42.4 36.28,39.48 32.47,35.66 32.47,34.65 30.06,32.24 v29.43,32.24 | v22.82,32.24 21.3,30.71 v19.27,30.71
  Bottom 0.254: J4.92 17.23,28.68 v19.27,30.71 | v22.82,32.24 v29.43,32.24
N$25
  Bottom 0.254: J3.60 51.27,73.35 50.29,72.38 45.62,72.38 44.78,71.53 44.78,60.73 45.14,60.37 45.14,59.35 45.17,59.32 45.15,59.3 U1.P60
N$26
  Bottom 0.254: U1.P13 43.65,29.7 39.33,25.51 39.33,21.19 45.17,15.35 46.83,15.35 47.71,14.46 47.71,8.87 43.65,4.8 J1.13
N$27
  Top 0.254: U1.P91 22.06,43.67 16.98,38.59 16.98,32.74 15.46,31.22 J4.91
N$28  (via drill 0.3)
  Top 0.254: v54.83,16.49 R6.2
  Bottom 0.254: v54.83,16.49 54.83,12.04 55.08,11.54 55.08,2.01 55.97,1.12 70.19,1.12 71.59,2.52 J1.24
N$29  (via drill 0.3)
  Top 0.254: R8.2 45.17,17.63 v45.94,16.87 | 72.61,4.8 J1.25 | 72.61,4.8 72.35,5.06 | v52.41,6.46 52.41,5.95 52.79,5.57 71.84,5.57 72.61,4.8
  Bottom 0.254: v45.94,16.87 47.59,16.87 48.48,15.85 49.49,14.84 50.76,14.84 52.41,13.19 v52.41,6.46
N$31
  Bottom 0.254: U1.P37 55.47,44.67 54.57,45.57 54.57,51.16 56.73,53.32 59.4,53.32 59.91,52.81 59.91,48.75 68.8,39.6 68.8,38.08 70.83,36.3 J2.37
N$32  (via drill 0.3)
  Top 0.254: R4.2 64.66,18.21 v64.73,18.14
  Bottom 0.254: v64.73,18.14 65.49,17.38 65.49,12.3 69.05,8.74 J1.23
N$33  (via drill 0.3)
  Top 0.254: v57.95,60.88 57.95,64.09 v57.91,65.64 | J3.61 48.73,74.34 48.73,74.33 51.38,71.68 v57.37,71.68
  Bottom 0.254: U1.P61 44.65,54.14 45.35,53.44 49.87,53.44 49.87,53.5 57.25,60.88 v57.95,60.88 | v57.95,60.88 | v57.91,65.64 57.91,71.14 v57.37,71.68
N$34
  Bottom 0.254: U1.P39 53.53,45.67 53.48,45.71 52.63,45.71 52.02,46.32 52.02,50.71 55.26,53.94 59.76,53.94 60.65,53.06 60.65,51.05 70.32,41.38 J2.39
N$35  (via drill 0.5)
  Top 0.254: J4.90 v15.71,33.76
  Bottom 0.254: v15.71,33.76 18.5,33.76 20.28,35.54 27.65,35.54 30.7,38.59 30.7,43.17 U1.P90
N$36
  Top 0.254: 43.71,74.4 43.72,74.41 | 43.71,74.4 J3.63 | U1.P63 43.65,74.34 43.71,74.4
N$37  (via drill 0.3)
  Top 0.254: J1.12 41.11,4.04 42.51,5.44 42.51,12.93 42.76,13.19 43.02,13.19 v43.14,13.31
  Bottom 0.254: U1.P12 43.15,33.01 42.38,32.24 36.79,32.24 35.52,30.97 35.52,23.35 43.14,15.73 v43.14,13.31
N$39
  Bottom 0.254: U1.P89 34.77,44.67 36.03,43.41 36.03,38.97 35.27,38.2 31.59,38.2 27.77,34.4 22.06,34.4 20.54,32.87 15.33,32.87 14.82,33.38 14.82,35.66 14.19,36.3 J4.89
N$40  (via drill 0.3)
  Top 0.254: U1.P28 55.62,40.15 55.62,38.06 58.3,35.38 58.81,34.85 69.05,24.62 v69.05,16.49
  Bottom 0.254: v69.05,16.49 69.05,15.47 71.08,13.44 J2.28
N$42
  Top 0.406: BOOTST.8 62.68,85.85 58.14,85.85 56.63,87.35 50.25,87.35 49.44,86.54 R10.1
N$43  (via drill 0.3)
  Top 0.254: U1.P30 52.51,40.09 52.51,37.85 63.72,26.65 v63.72,24.36
  Bottom 0.254: v63.72,24.36 69.56,18.52 J2.30
N$44  (via drill 0.3)
  Top 0.254: U1.P31 54.6,40.67 54.6,37.99 67.78,24.81 67.78,23.85 | v67.78,23.35 67.78,23.85 | 67.78,23.85 67.78,24.11
  Bottom 0.254: J2.31 | J2.31 | 71.34,21.06 70.83,21.06 | 71.34,21.06 J2.31 | 71.34,21.06 69.56,21.06 69.3,21.06 67.78,22.58 v67.78,23.35
N$45
  Top 0.254: J2.32 72.86,23.6 72.61,23.85 72.61,29.44 71.72,30.33 71.72,40.87 70.42,42.17 U1.P32
N$46  (via drill 0.3)
  Top 0.254: U1.P33 53.58,42.67 51.65,40.74 51.65,37.7 v62.83,26.52
  Bottom 0.254: v62.83,26.52 63.21,26.14 J2.33
N$47  (via drill 0.3)
  Top 0.254: U1.P34 56.6,42.17 56.6,38.59 57.62,37.57 64.1,37.57 v65.75,35.92
  Bottom 0.254: J2.34 72.1,28.68 69.18,31.6 69.18,32.49 v65.75,35.92
N$48
  Top 0.254: U1.P35 71.46,43.67 72.35,42.78 72.35,31.85 72.99,31.22 J2.35
N$49  (via drill 0.3)
  Top 0.254: v54.1,85.92 v54.12,85.91
  Top 0.406: R11.1 v54.1,85.92
  Bottom 0.254: 61.23,85.85 61.23,85.84 | 59.09,85.91 59.15,85.85
  Bottom 0.406: BOOTST.6 65.23,85.84 61.23,85.84 | 59.15,85.85 61.23,85.85 | v54.12,85.91 59.09,85.91
N$50
  Bottom 0.254: U1.P36 53.59,44.17 53.57,44.19 51.69,42.31 51.69,39.82 52.92,38.59 56.6,38.59 57.62,37.57 67.27,37.57 71.08,33.76 J2.36
N$51
  Top 0.254: U1.P88 21.79,45.17 15.46,38.84 13.19,38.82 J4.88
N$52
  Bottom 0.254: U1.P87 31.94,45.67 32.73,46.46 32.73,51.79 31.97,52.56 25.36,52.56 20.79,47.98 20.79,45.44 16.73,41.38 J4.87
N$53
  Top 0.254: U1.P2 37.96,35.03 37.05,35.03 33.24,31.22 33.24,29.19 18.5,14.46 18.5,9.63 15.71,6.84 J1.2
N$54
  Top 0.254: U1.P38 70.94,45.17 70.95,45.19 71.21,45.19 72.86,43.54 72.86,39.09 73.11,38.84 J2.38
N$55  (via drill 0.3)
  Top 0.254: v58.93,52.39 v61.91,52.39
  Bottom 0.254: U1.P40 56.6,47.17 56.6,51.67 57.32,52.39 v58.93,52.39 | J2.40 | J2.40 70.93,43.92 68.84,46.02 62.47,52.39 v61.91,52.39
N$56
  Top 0.254: U1.P41 73.92,46.67 J2.41
N$57
  Top 0.254: JP5.1 3.02,22.76 R7.1
N$58  (via drill 0.3)
  Top 0.254: U1.P43 56.61,48.68 56.61,51.67 58.77,53.82 v62.4,53.82
  Bottom 0.254: v62.4,53.82 63.22,53.82 65.52,51.55 74.18,51.55 | 74.18,51.55 74.17,51.54 J2.43 | 74.18,51.55 74.22,51.59
N$59
  Top 0.254: U1.P44 63.4,48.17 66.51,51.29 66.51,53.83 66.76,54.08 J2.44
N$60  (via drill 0.3)
  Top 0.254: U1.P45 53.6,48.74 52.61,49.73 52.61,50.78 57.04,55.2 57.04,56.29 v57.37,56.62
  Bottom 0.254: v57.37,56.62 J2.45
N$62
  Top 0.254: U1.P47 63.25,49.67 65.02,51.45 65.02,54.51 72.17,61.66 74.09,61.66 J2.47
N$63  (via drill 0.3)
  Top 0.254: U1.P48 53.6,51 59.48,56.86 65.2,62.58 v67.55,62.58
  Bottom 0.254: v67.55,62.58 70.81,62.58 72.43,64.2 74.07,64.2 74.11,64.24 J2.48
N$66
  Top 0.254: J3.51 66.78,67.12 50.78,67.12 49.68,66 49.68,59.18 49.62,59.12 | 49.62,59.12 49.62,59.11 | U1.P51 49.62,59.12
N$67
  Bottom 0.254: U1.P52 49.15,55.15 49.25,55.26 50.61,55.26 59.88,64.53 65.24,64.53 65.24,64.49 71.59,70.91 71.59,71.23 | 71.59,74.44 J3.52 | 71.59,71.24 71.59,74.44 | 71.59,74.44 71.68,74.52
  Bottom 0.305: 71.59,71.23 71.59,71.24
N$68
  Bottom 0.254: U1.P53 51.47,57.12 59.65,65.02 61.93,65.05 69.07,71.71 69.07,74.38 J3.53 | J3.53 | J3.53
N$69
  Bottom 0.254: 25.87,54.08 25.62,54.08 19.52,47.98 19.52,45.7 17.74,43.92 J4.86
  Bottom 0.305: U1.P86 34.32,46.17 35.04,46.89 35.04,51.21 32.18,54.09 25.87,54.08
N$70
  Top 0.254: 66.66,74.4 66.67,74.41 | 66.66,74.4 J3.54 | 66.66,74.4 66.53,74.28 66.53,72.36 62.31,68.16 50.23,68.16 48.25,66.15 48.25,59.25 48.15,59.15 U1.P54
N$71  (via drill 0.3)
  Top 0.254: U1.P55 48.67,54.11 49.59,54.11 50.25,54.77 50.25,54.97 54.38,59.17 54.37,64.82 55.95,66.37 v60.03,66.37 | v60.02,69.72 61.46,69.72 63.97,72.24 J3.55
  Bottom 0.254: v60.03,66.37 v60.02,69.72 | v60.02,69.72
N$72  (via drill 0.3)
  Top 0.254: U1.P56 48.15,56.13 49.84,56.13 53.33,59.62 v53.33,60.39
  Bottom 0.254: v53.33,60.39 58.89,65.51 60.67,65.51 61.43,66.27 J3.56 | J3.56 61.43,74.41 | J3.56
N$73
  Top 0.254: J3.57 58.89,74.39 58.93,74.34 58.86,74.28 58.89,69.76 58.15,69.04 49.53,69.04 46.67,66.18 46.67,59.18 46.65,59.16 U1.P57
N$74  (via drill 0.3)
  Top 0.254: U1.P58 47.79,53.49 49.84,53.49 50.76,54.4 50.76,54.71 55.97,59.92 55.97,64.48 v56,64.51
  Bottom 0.254: v56,64.51 55.98,65.06 56,65.25 56,73.15 56.33,73.57 56.33,74.43 56.35,74.42 J3.58
N$75
  Bottom 0.254: U1.P59 46.65,58.12 50.61,58.12 51.61,59.12 52.35,59.86 52.32,60.77 52.37,72.95 J3.59
N$80  (via drill 0.3)
  Top 0.254: U1.P80 35.06,50.53 35.06,52.48 33.6,53.95 33.59,53.95 30.86,56.68 30.86,56.71 v27.39,60.18
  Bottom 0.254: J4.80 19.52,59.16 20.54,60.18 v27.39,60.18
N$81
  Top 0.254: U1.P79 23.91,49.67 22.24,51.33 22.24,59.74 20.28,61.7 J4.79
N$84  (via drill 0.3)
  Top 0.254: U1.P78 31.7,51.79 27.05,56.45 27.05,56.46 24.35,59.16 v24.35,61.19 | J4.78 13.17,64.22 14.26,64.22 15.77,62.72 18.76,62.72 v19.01,62.72
  Bottom 0.254: v24.35,61.19 24.35,61.7 23.33,62.72 v19.01,62.72
N$86  (via drill 0.3)
  Top 0.254: U1.P77 33.7,52.45 33.6,52.45 26.12,59.92 26.12,61.45 v25.62,62.46 | 13.01,66.79 13.02,66.78 J4.77 14.44,66.78 17.22,64 v22.15,64 | v22.15,64
  Bottom 0.254: v25.62,62.46 24.09,63.99 22.16,63.99 v22.15,64
N$87  (via drill 0.3)
  Top 0.254: v35.39,58.86 35.6,58.8 35.6,63.48 v35.61,63.49 v35.6,63.49
  Bottom 0.254: U1.P65 41.66,56.13 37.43,56.13 37.43,56.14 35.78,57.79 35.78,58.49 35.42,58.86 | J3.65 | J3.65 | v35.6,63.49 38.57,66.41 J3.65 | 35.42,58.86 | v35.39,58.86 35.42,58.86
N$88
  Top 0.254: U1.P66 42.15,68.28 J3.66
N$89  (via drill 0.3)
  Top 0.254: v33.45,64.25 33.45,60.71 v33.45,60.8 | v36.31,56.21 36.38,56.13 40.63,56.14 U1.P67
  Bottom 0.254: J3.67 33.49,64.29 v33.45,64.25 | v33.45,60.8 33.45,59.07 v36.31,56.21
N$90
  Bottom 0.254: U1.P68 40.16,58.11 37.19,58.11 30.96,64.34 30.96,74.41 | 30.96,74.41 30.96,74.42 | 30.96,74.41 J3.68
N$91
  Top 0.254: U1.P69 40.65,67.25 40.64,67.25 36.54,71.35 29.65,71.35 28.38,72.62 28.38,74.41 28.39,74.4 J3.69
N$92  (via drill 0.3)
  Top 0.254: v34.02,56.23 34.02,55.42 35.49,53.95 38.97,53.95 40.15,55.13 U1.P70
  Bottom 0.254: J3.70 25.87,64.38 v34.02,56.23
N$93  (via drill 0.3)
  Top 0.254: U1.P71 38.66,58.11 35.08,58.17 29.55,63.69 29.47,63.69 29.43,63.73 29.43,66.02 28.41,67.03 23.84,67.03 v23.33,67.54
  Bottom 0.254: v23.33,67.54 J3.71
N$94
  Top 0.254: 20.77,74.41 J3.72 | 20.77,74.41 20.77,72.8 23.74,69.83 36.03,69.83 39.08,66.78 39.08,66.53 39.15,66.45 U1.P72 | 20.77,74.41 20.71,74.48
N$95
  Bottom 0.254: J3.73 18.25,71.19 33.66,55.52 37.57,55.53 38.63,55.13 38.63,55.12 U1.P73
N$97
  Top 0.254: U1.P75 37.65,59.16 37.56,59.25 37.56,66.27 35.27,68.56 23.08,68.56 20.54,71.1 16.47,71.1 J3.75
O  (via drill 0.5)
  Top 0.254: U1.P96 31.92,41.17 32.73,40.36 32.73,38.84 23.08,29.19 23.08,24.11 v21.3,22.33 | v18.25,19.28 17.49,18.52 J4.96
  Top 0.305: JP10.2 6.82,17.25 9.87,17.25 11.14,18.52 J4.96
  Bottom 0.254: v18.25,19.28 v21.3,22.33
P1.0  (via drill 0.3)
  Top 0.254: U1.P14 44.15,36.29 44.92,37.06 50,37.06 60.92,26.14 v60.92,24.74 | v60.92,14.71 60.92,12.17 60.16,11.41 JP2.2 50.25,8.36 49.75,7.85 49.75,5.57 49.24,5.06 46.44,5.06 46.19,4.8 J1.14
  Bottom 0.254: v60.92,14.71 v60.92,24.74
P2.2  (via drill 0.3)
  Top 0.254: U1.P27 53.53,39.67 53.52,39.67 53.58,39.62 53.58,37.94 66.51,24.75 66.51,22.58 67.53,21.57 v67.53,16.62
  Bottom 0.254: J2.27 70.32,10.9 67.53,13.69 v67.53,16.62
RST  (via drill 0.5)
  Top 0.254: v21.3,32.24 21.3,36.55 23.84,39.09 25.23,39.09 | 25.23,39.09 29.62,39.09 U1.P100 | R5.1 25.23,39.22 25.23,39.09 | 5.55,7.6 JP6.2 | 7.58,5.57 5.55,7.6 | 7.58,5.57 9.52,5.57 C3.2 | 7.58,5.57 5.55,7.6
  Top 0.305: C3.2 10.45,5.64 J4.100
  Bottom 0.254: J4.100 14.95,8.36 16.47,9.88 16.47,19.28 21.3,24.11 v21.3,32.24
RST/NMI
  Top 0.254: JTAG.11 20.34,89.19 66.57,89.19 66.57,89.21 | 66.65,89.19 66.66,89.18 66.57,89.21 | 66.57,89.21 67.77,87.76 67.77,85.89 69.11,84.57 BOOTST.4
  Bottom 0.254: JP6.3 6.77,9.68 4.64,9.68 4.28,10.03 4.28,25.16 6.9,27.78 6.93,84.14 8.65,85.86 17.03,85.86 JTAG.11
TA2.0_TX  (via drill 0.3)
  Top 0.254: v71.07,66.82 71.07,64.23 62.78,55.93 60.08,55.93 55.6,51.46 U1.P49
  Top 0.406: BOOTST.1 74.76,87.11 78.07,83.8 78.07,69.19 75.65,66.78 J2.49
  Bottom 0.254: J2.49 74.09,66.82 v71.07,66.82
TA2.1_RX
  Top 0.254: U1.P50 62.35,51.17 63.65,52.47 63.65,55.67 71.93,63.92 71.93,67.11 74.15,69.32 | 74.15,69.32 74.27,69.45 | 74.15,69.32 J2.50
  Top 0.406: BOOTST.3 69.04,86.98 70.19,85.83 73.37,85.83 76.29,82.91 76.29,70.08 75.53,69.32 J2.50
TCK  (via drill 0.3)
  Top 0.254: v13.11,77.39 17.12,77.39 19.18,77.41 20.74,77.41 v22.06,77.39 | 9.44,27.33 9.44,27.32 | 9.44,27.33 R7.2 | v11.21,27.36 9.44,27.36 9.44,27.33
  Bottom 0.254: v13.11,77.39 11.21,75.48 11.2,62.63 11.2,44.41 11.21,44.09 v11.21,27.36 11.19,13.98 8.99,11.77 JP7.3 | v22.06,77.39 22.06,85.73 23.43,87.05 23.38,87.05 JTAG.7
TDI  (via drill 0.3)
  Top 0.254: v10.25,79.56 v29.65,79.56
  Bottom 0.254: JP9.3 9.43,17.32 9.43,78.74 v10.25,79.56 | JTAG.3 28.41,87.11 28.41,87.12 29.65,85.88 v29.65,79.56
TDO  (via drill 0.3)
  Top 0.254: JP10.3 6.81,19.8 4.7,19.8 4.28,19.38 4.28,9.59 3.14,8.44 3.09,8.44 JP6.1 | v9.16,81.06 v32.81,81.06
  Bottom 0.254: JP10.3 6.84,19.77 6.84,24.59 8.62,26.31 8.62,80.4 v9.16,81.06 | JTAG.1 30.97,87.1 32.81,85.25 v32.81,81.06
TEST/SBWTCK  (via drill 0.3)
  Top 0.254: JTAG.8 22.07,85.82 11.36,85.82 v10.04,84.5 | U1.P95 33.96,41.67 35.01,40.62 35.01,39.09 24.85,28.93 24.85,22.58 23.33,21.06 J4.95 | JP5.2 JP5.3
  Top 0.305: 8.06,21.04 JP5.3 J4.95
  Bottom 0.254: BOOTST.7 62.29,88.78 25.54,88.78 24.55,87.79 24.55,85.78 23.41,84.64 23.36,84.64 23.36,84.59 JTAG.8 | v10.04,84.5 7.81,82.27 7.81,27.06 5.52,24.77 5.52,21.09 JP5.2
TMS  (via drill 0.3)
  Top 0.254: v11.66,78.64 v27.12,78.64
  Bottom 0.254: JP8.3 10.31,15.66 10.28,77.2 v11.66,78.64 | JTAG.5 25.87,87.08 27.12,85.82 v27.12,78.64
UCA0RXD
  Bottom 0.254: U1.P16 45.15,29.42 41.62,26.01 41.62,19.79 45.3,16.11 47.08,16.11 48.73,14.46 48.86,14.33 50.13,14.33 51.27,13.19 J1.16
UCA0TXD  (via drill 0.3)
  Top 0.254: v50,38.33 v45.94,38.33 | v59.14,10.39 55.08,10.39 v54.19,9.5
  Bottom 0.254: U1.P17 45.65,38.05 v45.94,38.33 | v50,38.33 51.52,38.33 58.89,30.97 58.89,16.74 59.14,16.49 v59.14,10.39 | v54.19,9.5 54.19,3.66 J1.17
VASYS
  Top 0.254: 36.03,22.33 36.03,20.55 32.22,16.74 32.22,5.06 32.47,4.8 34.51,4.8 J1.10 | 36.16,22.38 C4.1 36.66,22.63 36.66,23.35 38.32,25 C16.1 | U1.P10 42.15,27.18 41.24,26.27 39.46,26.27 38.95,25.76 38.95,25.05 C16.1 | C16.1 39.08,25.18
  Top 0.406: 36.03,22.33 C4.1
VCC  (via drill 0.3)
  Top 0.254: R11.2 52.05,84.05 52.01,84.1 51.98,84.08
  Top 0.406: v4.51,82.43 7.05,82.42 9.98,82.42 37.89,82.42 39.04,82.43 41.11,82.43 | 51.98,84.08 R10.2 47.8,82.43 41.11,82.43 | 41.11,82.43 JP3.2
  Bottom 0.254: 3.04,69.27 J5.1 | v4.51,82.43 4.51,82.34 4.52,82.33 4.48,82.29
  Bottom 0.406: 4.48,82.29 4.48,72.47 4.49,70.69 4.49,70.71 3.04,69.27 3.01,69.27 JP1.1
VCORE  (via drill 0.3)
  Top 0.254: v54.32,33.89 62.7,25.38 62.7,22.71 62.78,22.46 C10.1 R4.1
  Bottom 0.254: U1.P23 52.98,35.22 v54.32,33.89
VEREF+  (via drill 0.3)
  Top 0.254: U1.P15 44.65,32.73 44.16,32.24 36.79,32.24 36.28,31.73 v36.28,30.46 | J1.15 48.73,2.64 47.84,1.76 45.55,1.76 44.92,2.39 44.92,7.09 43.78,8.23 C12.1 44.21,9 44.79,9 v45.3,9.5
  Bottom 0.254: v36.28,30.46 36.28,23.35 45.17,14.58 45.3,14.46 v45.3,9.5
VREF
  Top 0.254: J1.7 28.41,4.04 27.9,4.55 27.9,13.57 35.14,20.81 35.14,22.96 39.28,27.1 C7.1 39.46,28.22 39.46,29.44 40.6,30.59 40.6,31.17 U1.P7
XIN
  Top 0.254: R6.1 C2.1 Q1.2
  Bottom 0.406: U1.P24 49.9,33.22 52.54,30.59 Q1.2
XOUT
  Top 0.254: R8.1 C1.1 Q1.1
  Bottom 0.254: Q1.1 47.47,28.84 U1.P25
XTLGND1  (via drill 0.8 pad 0.3)
  Top 0.254: v50.1,17.22 50.1,17.27 | v50.1,17.22 50.11,17.22 | 50,17.25 50.07,17.25 v50.1,17.22 | 50,17.25 49.24,17.25 | 50,17.25 50.25,17.25 50.89,17.25 | v50.1,17.22 50,17.25 | v50.1,17.22 50,17.19 | C1.2 49.68,19.36 Q1.GND@0 50.37,19.68 50.89,19.16 52.34,19.16 C2.2
  Top 0.406: 50.89,19.16 50.1,19.16 v50.1,17.22 | 49.24,17.25 50.25,17.25
  Bottom 0.406: 48.76,17.25 51.14,17.25 | 50,26.29 50,28.68
  pour Bottom: 52.03,17.64 55.85,17.64 55.78,21.37 55.78,27.49 50.06,28.02 44.07,27.38 43.82,27.01 43.82,18.63 44.3,18 44.41,18.01 47.33,17.89 48.48,16.74 48.98,16.11 49.24,15.85 51.78,15.85 52.03,17.63

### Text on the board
tNames: Vcc | DVDSYS | int | ext | MSP-TS430PZ100B | Rev.: 1.1 RoHS | 1 | SBW | JTAG | DVCC | AUXVCC | GND | AUXVCC3 | AUXVCC2 | AUXVCC1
